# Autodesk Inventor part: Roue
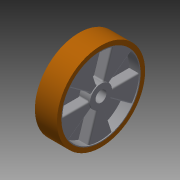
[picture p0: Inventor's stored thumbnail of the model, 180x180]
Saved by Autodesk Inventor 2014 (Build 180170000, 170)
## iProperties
Created: 2015-07
Part Number: Roue
Material: Générique
Document SubType Name: Modeling
Designer: OL
Density: 1 g/cm^3
Appearance: Par défaut
Author: OL
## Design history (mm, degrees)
sketch "Esquisse1"
  geometry: C1 r 90 at (0, 0); 1 further point
  constraints: 1 centre point, 1 coincident
  dimensions: "d0" = 180 diameter of C1
extrude "Extrusion1" new body sketch "Esquisse1" stored distance "d2" = 50; taper "d3" = 0 deg
sketch "Esquisse2"
  geometry: C1 r 90 at (0, 0) reference; C2 r 25 at (0, 0); C3 r 88 at (0, 0)
  constraints: 2 centre point, 2 coincident
  dimensions: "d4" = 176 diameter of C3; "d7" = 50 diameter of C2
extrude "Extrusion2" cut sketch "Esquisse2" distance "d8" = 2; taper "d9" = 0 deg
sketch "Esquisse3"
  geometry: L1 (-14.695, 20.225)-(-51.725, 71.193); L2 (0, 25)-(0, 88); L3 (23.776, -7.725)-(83.693, -27.193); L4 (14.695, -20.225)-(51.725, -71.193); L5 (0, -25)-(0, -88); L6 (-14.695, -20.225)-(-51.725, -71.193); L7 (-23.776, -7.725)-(-83.693, -27.193); L8 (-23.776, 7.725)-(-83.693, 27.193); L9 (14.695, 20.225)-(51.725, 71.193); L10 (23.776, 7.725)-(83.693, 27.193); 2 further points
  constraints: 20 end point, 2 collinear, 22 other
  dimensions: "d10" = 36 deg angle of L2 L1; "d11" = 36 deg angle of L8 L1; "d12" = 36 deg angle of L8 L7; "d13" = 36 deg angle of L7 L6; "d14" = 36 deg angle of L6 L5; "d15" = 36 deg angle of L5 L4; "d16" = 36 deg angle of L4 L3
extrude "Extrusion3" cut sketch "Esquisse3" distance "d17" = 22; taper "d18" = 0 deg
fillet "Congé1" dims "d19" = 3
sketch "Esquisse4"
  geometry: C1 r 90 at (0, 0) reference; C2 r 88 at (0, 0); C3 r 25 at (0, 0)
  constraints: 2 centre point, 2 coincident
  dimensions: "d20" = 176 diameter of C2; "d22" = 50 diameter of C3
extrude "Extrusion4" cut sketch "Esquisse4" distance "d23" = 2; taper "d24" = 0 deg
sketch "Esquisse5"
  geometry: C1 r 25 at (0, 0) reference; C2 r 12.5 at (0, 0)
  constraints: 1 centre point, 1 coincident
  dimensions: "d26" = 25 diameter of C2
extrude "Extrusion5" cut sketch "Esquisse5" stored distance "d28" = 2; taper "d29" = 0 deg
sketch "Esquisse6"
  geometry: C1 r 90 at (0, 0); C2 r 100 at (0, 0); 1 further point
  constraints: 2 centre point, 2 coincident
  dimensions: "d30" = 200 diameter of C2; "d34" = 180 diameter of C1
extrude "Extrusion6" join sketch "Esquisse6" stored distance "d32" = 50.1; taper "d33" = 0 deg
mirror "Symétrie2"
fillet "Congé2" dims "d35" = 3
node "Solide1"
